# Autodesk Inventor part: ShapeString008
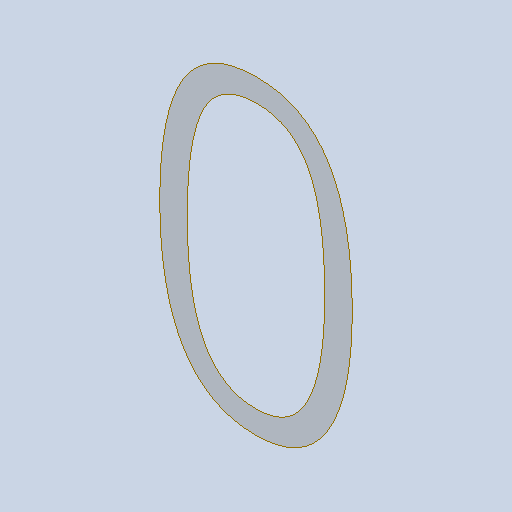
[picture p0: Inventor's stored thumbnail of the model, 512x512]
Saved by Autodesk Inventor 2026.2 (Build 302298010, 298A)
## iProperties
Created: 2026-10
Part Number: ShapeString008
Material: Générique
Document SubType Name: Modeling
Designer: mel
Density: 1 g/cm^3
Appearance: Par défaut
Author: mel
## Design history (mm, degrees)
feature "Composite1"
body "Srf1"
